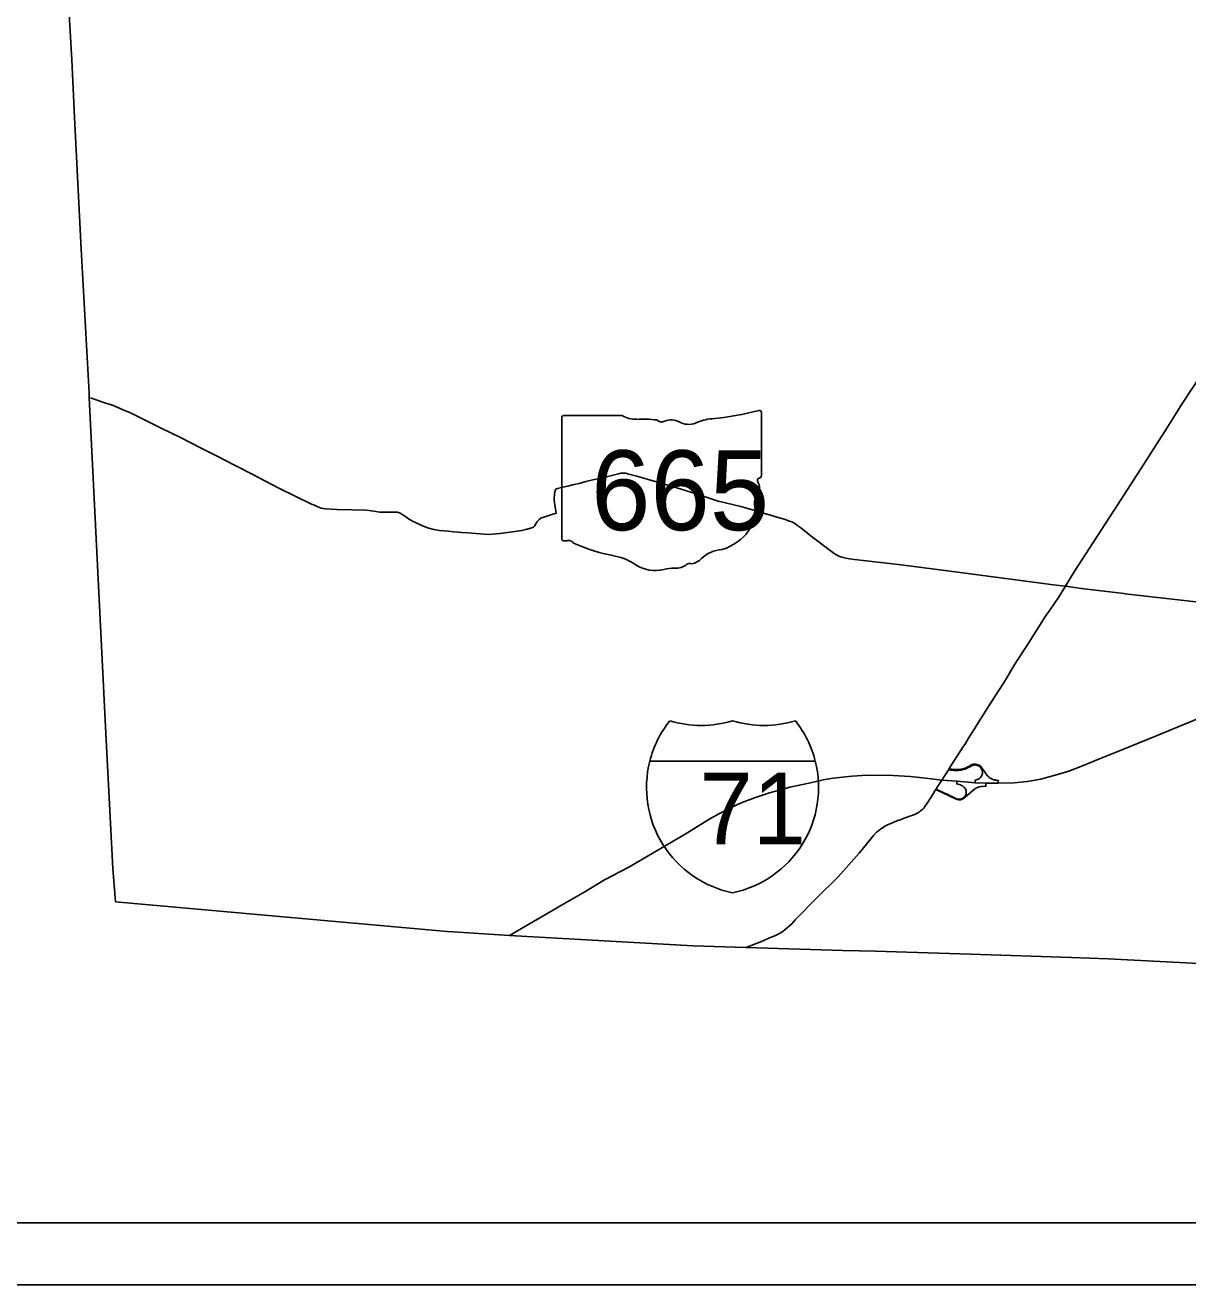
# Model space of a CAD drawing. Extents: x -7.1 to 34, y 0 to 22.
# Drawn here: x 2.355 to 4.231, y 14 to 16.034 of the extents above; entities that cross this region are included whole.
import ezdxf

# ---------------------------------------------------------------- set-up
doc = ezdxf.new("R2010")
doc.units = 0
for name, color, linetype in [('GM_X_County', 7, 'Continuous'), ('GM_X_Interchange_Ramps', 7, 'Continuous'), ('GM_X_Interstate_Route', 7, 'Continuous'), ('GM_X_Interstate_Shield', 7, 'Continuous'), ('GM_X_State_Route', 7, 'Continuous'), ('GM_X_State_Shield', 7, 'Continuous'), ('GM_X_US_Route', 7, 'Continuous'), ('SH_Data', 7, 'Continuous')]:
    doc.layers.add(name, color=color, linetype=linetype)

msp = doc.modelspace()

# ---------------------------------------------------------------- linework, layer by layer
at = {"layer": 'GM_X_County'}
msp.add_lwpolyline([(4.3432, 14.5137), (4.1028, 14.5264), (4.0433, 14.5282), (3.8804, 14.5337), (3.7274, 14.5387), (3.6744, 14.5398), (3.518, 14.5447), (3.4331, 14.5474), (3.1368, 14.564), (3.0545, 14.5691), (3.0359, 14.5706), (2.5009, 14.6184), (2.4963, 14.6721), (2.4852, 14.8903), (2.4585, 15.4323), (2.4581, 15.4393), (2.4455, 15.6718), (2.4349, 15.885), (2.4304, 15.9776), (2.4197, 16.1634)], dxfattribs=at)
at = {"layer": 'GM_X_Interchange_Ramps'}
for points in [[(3.8453, 14.8321), (3.8463, 14.8314), (3.8484, 14.831), (3.8504, 14.8308), (3.8525, 14.8306), (3.8544, 14.8305), (3.8561, 14.8304), (3.8579, 14.8303), (3.8594, 14.8304), (3.8613, 14.8305), (3.8633, 14.8307), (3.8652, 14.831), (3.8671, 14.8313), (3.8688, 14.8318), (3.8703, 14.8322), (3.8719, 14.8327), (3.8732, 14.8332), (3.8747, 14.834), (3.8763, 14.8348), (3.8778, 14.8356), (3.8793, 14.8364), (3.882, 14.8379), (3.8837, 14.8386), (3.8859, 14.8391), (3.8877, 14.8393), (3.8896, 14.8391), (3.8915, 14.8386), (3.8933, 14.8378), (3.8948, 14.8369), (3.8962, 14.8357), (3.8972, 14.8346), (3.8981, 14.8332), (3.8988, 14.8318), (3.8994, 14.8303), (3.8996, 14.8288), (3.8998, 14.8272), (3.8997, 14.8256), (3.8994, 14.8243), (3.8989, 14.8227), (3.8982, 14.8212), (3.8978, 14.8205), (3.8968, 14.8192), (3.896, 14.8184), (3.895, 14.8175), (3.8937, 14.8166), (3.8927, 14.8161), (3.8916, 14.8157), (3.8881, 14.8148), (3.8878, 14.8103)], [(3.9253, 14.8097), (3.9254, 14.8143), (3.9222, 14.8145), (3.9209, 14.8147), (3.9195, 14.815), (3.9182, 14.8154), (3.9167, 14.8159), (3.9154, 14.8164), (3.9137, 14.8173), (3.9125, 14.818), (3.9114, 14.8187), (3.9104, 14.8195), (3.9092, 14.8205), (3.9082, 14.8215), (3.9076, 14.8221), (3.9069, 14.8229), (3.9059, 14.8243), (3.9053, 14.8252), (3.9044, 14.8266), (3.9034, 14.8279), (3.9025, 14.8293), (3.9016, 14.8307), (3.9004, 14.8324), (3.8994, 14.8338), (3.8985, 14.8351), (3.8972, 14.8367), (3.8959, 14.8378), (3.8946, 14.8387), (3.8928, 14.8396), (3.8908, 14.8402), (3.889, 14.8406), (3.8869, 14.8406), (3.885, 14.8404), (3.8833, 14.8399), (3.882, 14.8394), (3.8809, 14.8388), (3.8791, 14.8378), (3.8776, 14.837), (3.8761, 14.8362), (3.8747, 14.8355), (3.8733, 14.8348), (3.8717, 14.8341), (3.8701, 14.8336), (3.8682, 14.833), (3.8668, 14.8327), (3.8648, 14.8323), (3.8627, 14.832), (3.8607, 14.8318), (3.8588, 14.8317), (3.857, 14.8317), (3.8553, 14.8318), (3.8538, 14.8319), (3.8521, 14.832), (3.8502, 14.8322), (3.8484, 14.8324), (3.8472, 14.8326), (3.8461, 14.8334)], [(3.8246, 14.7997), (3.8267, 14.7984), (3.8565, 14.7843), (3.8588, 14.7834), (3.8609, 14.7831), (3.8627, 14.783), (3.8645, 14.7832), (3.8662, 14.7836), (3.8674, 14.784), (3.8693, 14.7851), (3.8724, 14.7877), (3.8869, 14.8), (3.8886, 14.8012), (3.8904, 14.8023), (3.8919, 14.803), (3.893, 14.8035), (3.8947, 14.804), (3.8972, 14.8045), (3.8995, 14.8047), (3.9054, 14.805), (3.9054, 14.8097)], [(3.8586, 14.8132), (3.8582, 14.8086), (3.862, 14.8077), (3.8642, 14.8071), (3.866, 14.8063), (3.8677, 14.8053), (3.8692, 14.8042), (3.8707, 14.8028), (3.8716, 14.8018), (3.8724, 14.8007), (3.8731, 14.7991), (3.8735, 14.7975), (3.8737, 14.7958), (3.8737, 14.7942), (3.8734, 14.7928), (3.8729, 14.7911), (3.8724, 14.7899), (3.8716, 14.7887), (3.8707, 14.7876), (3.8696, 14.7865), (3.8682, 14.7856), (3.8666, 14.7848), (3.8648, 14.7843), (3.8626, 14.784), (3.8602, 14.7841), (3.8581, 14.7847), (3.8558, 14.7856), (3.8541, 14.7865), (3.8515, 14.7877), (3.8492, 14.7888), (3.8465, 14.7901), (3.8438, 14.7913), (3.8417, 14.7924), (3.8395, 14.7934), (3.8366, 14.7948), (3.8342, 14.7959), (3.8317, 14.7971), (3.8295, 14.7981), (3.8271, 14.7993), (3.8252, 14.8005)]]:
    msp.add_lwpolyline(points, dxfattribs=at)
at = {"layer": 'GM_X_Interstate_Route'}
for points in [[(4.1211, 14.8623), (4.1234, 14.8633), (4.1817, 14.887), (4.2584, 14.9184), (4.3181, 14.9432), (4.3753, 14.9669), (4.3984, 14.9783), (4.4099, 14.985), (4.4149, 14.9883)], [(3.8343, 14.8148), (3.8586, 14.8132), (3.8878, 14.8103), (3.9054, 14.8097), (3.9253, 14.8097), (3.9509, 14.8103), (3.9717, 14.8125), (3.9942, 14.8161), (4.0207, 14.824), (4.0374, 14.8289), (4.0531, 14.8346), (4.0941, 14.8511), (4.1211, 14.8623)], [(3.1368, 14.564), (3.2241, 14.6148), (3.258, 14.6346), (3.2901, 14.6537), (3.3293, 14.6744), (3.42, 14.7277), (3.4443, 14.7424), (3.4607, 14.7529), (3.4763, 14.7612), (3.4941, 14.7704), (3.5104, 14.7779), (3.5318, 14.7861), (3.5561, 14.7943), (3.5892, 14.8035), (3.6223, 14.8104), (3.6425, 14.8152), (3.659, 14.8177), (3.6843, 14.8207), (3.6893, 14.8211), (3.7051, 14.8222), (3.7201, 14.823), (3.7555, 14.8224), (3.7834, 14.8205), (3.8082, 14.818), (3.8343, 14.8148)]]:
    msp.add_lwpolyline(points, dxfattribs=at)
at = {"layer": 'GM_X_Interstate_Shield'}
for p, q in [((3.363, 14.8455), (3.63, 14.8455)), ((3.63, 14.8455), (3.363, 14.8455)), ((3.63, 14.8455), (3.363, 14.8455))]:
    msp.add_line(p, q, dxfattribs=at)
for centre, start, end in [((3.5312, 14.8029), 141.669, 165.8066), ((3.4458, 15.0765), 253.0091, 286.9909), ((3.5472, 15.0765), 253.0091, 286.9909), ((3.4618, 14.8029), 14.1934, 38.331), ((3.5312, 14.8029), 165.8066, 258.463), ((3.4618, 14.8029), 281.537, 14.1934)]:
    msp.add_arc(centre, 0.1735, start, end, dxfattribs=at)
at = {"layer": 'GM_X_State_Route'}
for points in [[(2.4603, 15.4319), (2.4698, 15.4286), (2.4805, 15.425), (2.4885, 15.4224), (2.4944, 15.4204), (2.5006, 15.4181), (2.5085, 15.4147), (2.5156, 15.4117), (2.5211, 15.4093), (2.528, 15.406), (2.536, 15.4021), (2.5744, 15.383), (2.6055, 15.3677), (2.6402, 15.3501), (2.6661, 15.3372), (2.6931, 15.3233), (2.7214, 15.3087), (2.753, 15.2923), (2.7657, 15.2855), (2.8172, 15.2604), (2.8217, 15.2586), (2.8261, 15.2566), (2.83, 15.255), (2.8327, 15.2539), (2.8359, 15.2531), (2.8402, 15.2527), (2.8581, 15.2518), (2.8823, 15.251), (2.9054, 15.2504), (2.9137, 15.2497), (2.9209, 15.2486), (2.927, 15.2471), (2.9352, 15.2472), (2.9516, 15.2472), (2.9557, 15.2472), (2.9573, 15.247), (2.9589, 15.2465), (2.9603, 15.2457), (2.9669, 15.2413), (2.9737, 15.2368), (2.9813, 15.2323), (2.984, 15.231)], [(3.0599, 15.2148), (3.0692, 15.214), (3.1023, 15.2114), (3.1217, 15.213), (3.1417, 15.2155), (3.1563, 15.2178), (3.1632, 15.2195), (3.1726, 15.222), (3.1755, 15.2234), (3.1773, 15.2252), (3.1788, 15.2279), (3.18, 15.23), (3.1815, 15.2325), (3.1827, 15.234), (3.1846, 15.2356), (3.1873, 15.2376), (3.2035, 15.2428), (3.2121, 15.2457), (3.2104, 15.2557), (3.2087, 15.267), (3.2086, 15.2681), (3.209, 15.278), (3.2109, 15.2836), (3.2117, 15.2849), (3.2275, 15.2886), (3.2328, 15.29), (3.2382, 15.2914), (3.2437, 15.2926), (3.2492, 15.2939), (3.2598, 15.2967), (3.2709, 15.2993), (3.2819, 15.3018), (3.2976, 15.3056)], [(3.2976, 15.3056), (3.3123, 15.3091), (3.3161, 15.3101), (3.321, 15.3106), (3.3243, 15.3101), (3.3272, 15.3094), (3.3419, 15.3053), (3.3754, 15.2958), (3.3996, 15.2888)], [(3.3996, 15.2888), (3.4206, 15.2826), (3.4434, 15.2753), (3.4621, 15.2688), (3.4733, 15.2653), (3.4851, 15.2622), (3.5101, 15.2565), (3.5212, 15.2533), (3.5466, 15.2459), (3.5814, 15.2357), (3.5885, 15.2331), (3.592, 15.2315), (3.5955, 15.2299), (3.599, 15.2277), (3.6015, 15.2259), (3.6048, 15.2235), (3.6087, 15.2204), (3.6211, 15.2105), (3.6562, 15.1836), (3.6605, 15.1807), (3.6641, 15.1784), (3.6681, 15.1766), (3.6727, 15.1749), (3.6795, 15.1733), (3.685, 15.1721), (3.6935, 15.1709), (3.7685, 15.1624), (3.8559, 15.1511), (4.0142, 15.1301), (4.0235, 15.1289), (4.0336, 15.1277)], [(2.984, 15.231), (2.995, 15.2258), (3.0041, 15.2222), (3.0145, 15.2193), (3.0239, 15.218), (3.0377, 15.2166), (3.0469, 15.2158), (3.0599, 15.2148)], [(4.0336, 15.1277), (4.0594, 15.1244), (4.128, 15.1159)], [(4.128, 15.1159), (4.1302, 15.1156), (4.2441, 15.1024), (4.269, 15.0995), (4.3292, 15.0924), (4.3936, 15.0847), (4.4548, 15.0771), (4.4622, 15.0762)]]:
    msp.add_lwpolyline(points, dxfattribs=at)
at = {"layer": 'GM_X_State_Shield'}
for p, q in [((3.221, 15.4001), (3.221, 15.2045)), ((3.3185, 15.4035), (3.2241, 15.4035)), ((3.5431, 15.306), (3.5431, 15.4083)), ((3.543, 15.3061), (3.5431, 15.306))]:
    msp.add_line(p, q, dxfattribs=at)
for centre, major_axis, start_param, end_param in [((3.2246, 15.4005), (0.00373, 0), 1.712693, 3.28349), ((3.3409, 15.4262), (0.0362, 0), 4.042523, 4.731795), ((3.3529, 15.2937), (0.1299, 0), 1.404758, 1.657858), ((3.3824, 15.4016), (0.0104, 0), 3.836095, 5.185415), ((3.3978, 15.379), (0.0217, 0), 0.950623, 2.079405), ((3.4719, 15.3438), (0.0687, 0), 1.699011, 2.107814), ((3.4283, 15.6701), (0.3416, 0), 4.814394, 5.042369), ((3.5395, 15.4088), (0.00359, 0), 6.141152, 7.989035), ((3.4258, 15.41), (0.0261, 0), 4.081561, 5.145723), ((3.5422, 15.2985), (0.00555, 0), 1.883978, 3.671073), ((3.5069, 15.2856), (0.0333, 0), 5.934695, 6.695948), ((3.5392, 15.3056), (0.00384, 0), 5.05454, 6.418171), ((3.5559, 15.2632), (0.0242, 0), 2.387724, 3.262537), ((3.4475, 15.2502), (0.0854, 0), 5.101752, 6.440018), ((3.2247, 15.2041), (0.00376, 0), 3.00124, 4.508301), ((3.2253, 15.2241), (0.0287, 0), 4.665946, 4.897461), ((3.2311, 15.1933), (0.0104, 0), 0.519207, 1.627899), ((3.3619, 15.369), (0.2467, 0), 4.195997, 4.488961), ((3.2884, 15.1167), (0.0772, 0), 0.823519, 1.323587), ((3.4242, 15.1856), (0.0276, 0), 4.937069, 5.64225), ((3.4835, 15.1496), (0.0468, 0), 1.647645, 2.488434), ((3.3719, 15.1923), (0.049, 0), 4.026481, 4.996735), ((3.4002, 15.1247), (0.0402, 0), 1.495662, 1.94098), ((3.4037, 15.1776), (0.0261, 0), 4.691044, 5.507374), ((3.4273, 15.1587), (0.00735, 0), 1.147584, 2.315152)]:
    msp.add_ellipse(centre, major_axis=major_axis, ratio=0.8, start_param=start_param, end_param=end_param, dxfattribs=at)
at = {"layer": 'GM_X_US_Route'}
for points in [[(4.2185, 15.4169), (4.314, 15.5614), (4.3415, 15.603), (4.3479, 15.6121), (4.3491, 15.6138)], [(4.2105, 15.4043), (4.2105, 15.4043), (4.2172, 15.4148), (4.2185, 15.4169), (4.2185, 15.4169)], [(4.11, 15.2475), (4.1122, 15.2508), (4.1601, 15.3248), (4.1972, 15.3832), (4.2105, 15.4043)], [(4.0336, 15.1277), (4.0403, 15.1384), (4.0476, 15.1508), (4.11, 15.2475)], [(3.9335, 14.9714), (3.9373, 14.9774), (3.9509, 15.0001), (3.9739, 15.0358), (4.0014, 15.0792), (4.0095, 15.0908), (4.0156, 15.0995), (4.0223, 15.1098), (4.0336, 15.1277)], [(3.8461, 14.8334), (3.868, 14.8678), (3.8722, 14.8741), (3.8775, 14.8825), (3.8871, 14.8975), (3.8946, 14.9098), (3.9197, 14.9496), (3.9335, 14.9714)], [(3.838, 14.8206), (3.8453, 14.8321), (3.8461, 14.8334)], [(3.8232, 14.7974), (3.8246, 14.7997), (3.8252, 14.8005), (3.8259, 14.8017), (3.8343, 14.8148), (3.838, 14.8206)], [(3.771, 14.7522), (3.7808, 14.7559), (3.7872, 14.7582), (3.7887, 14.7587), (3.7915, 14.7598), (3.7935, 14.7608), (3.7956, 14.7619), (3.7975, 14.7632), (3.7994, 14.7645), (3.8021, 14.7666), (3.8036, 14.768), (3.8055, 14.77), (3.807, 14.772), (3.8119, 14.7792), (3.8201, 14.7926), (3.8232, 14.7974)], [(3.5755, 14.5691), (3.5774, 14.5704), (3.5816, 14.5736), (3.592, 14.583), (3.5975, 14.5894), (3.6325, 14.6245), (3.6667, 14.6587), (3.7006, 14.6968), (3.7195, 14.7198), (3.7242, 14.7256), (3.7287, 14.7305), (3.7319, 14.7331), (3.7351, 14.7356), (3.7404, 14.7393), (3.7464, 14.7425), (3.7519, 14.745), (3.7567, 14.7468), (3.7618, 14.7488), (3.77, 14.7518), (3.771, 14.7522)], [(3.5406, 14.5534), (3.5472, 14.556), (3.5564, 14.5601), (3.5648, 14.5636), (3.5731, 14.5676), (3.5755, 14.5691)], [(3.518, 14.5447), (3.5241, 14.5469), (3.5361, 14.5517), (3.5406, 14.5534)]]:
    msp.add_lwpolyline(points, dxfattribs=at)
at = {"layer": 'SH_Data'}
for p, q in [((2.1, 14.1), (8.9, 14.1)), ((2, 14), (9, 14))]:
    msp.add_line(p, q, dxfattribs=at)

# ---------------------------------------------------------------- texts
at = {"layer": 'GM_X_Interstate_Shield'}
msp.add_text('71', height=0.11569, dxfattribs=at).set_placement((3.4431, 14.711))
at = {"layer": 'GM_X_State_Shield'}
msp.add_text('665', height=0.12885, dxfattribs=at).set_placement((3.2682, 15.2183))

doc.saveas('drawing.dxf')
